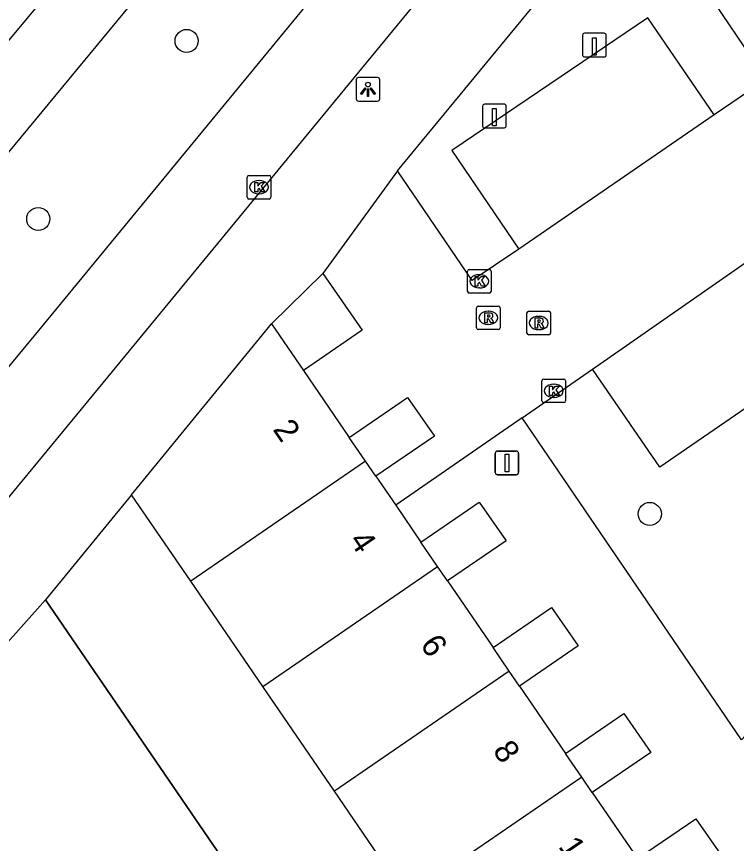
# Model space of a CAD drawing. Extents: x 155275 to 156263, y 382654 to 383635.
# Drawn here: x 155522.64 to 155553.1, y 382882.06 to 382917.07 of the extents above; entities that cross this region are included whole.
import ezdxf

# ---------------------------------------------------------------- set-up
doc = ezdxf.new("R2010")
doc.units = 0
for name, color, linetype in [('IMGEO_Afsluitpaal', 7, 'Continuous'), ('IMGEO_Boom', 7, 'Continuous'), ('IMGEO_Fietspad_gesloten', 7, 'Continuous'), ('IMGEO_Groenvoorziening', 7, 'Continuous'), ('IMGEO_Kolk', 7, 'Continuous'), ('IMGEO_Laadpaal', 7, 'Continuous'), ('IMGEO_Lichtpunt', 7, 'Continuous'), ('IMGEO_Muur', 7, 'Continuous'), ('IMGEO_Pand', 7, 'Continuous'), ('IMGEO_Pand_nummerreeks', 7, 'Continuous'), ('IMGEO_Parkeervlak_open', 7, 'Continuous'), ('IMGEO_Rijbaan_lokaal_gesloten', 7, 'Continuous'), ('IMGEO_Rijbaan_lokaal_open', 7, 'Continuous'), ('IMGEO_Rioolput', 7, 'Continuous'), ('IMGEO_Voetpad_open', 7, 'Continuous')]:
    doc.layers.add(name, color=color, linetype=linetype)

msp = doc.modelspace()

# ---------------------------------------------------------------- linework, layer by layer
at = {"layer": 'IMGEO_Afsluitpaal'}
for p, q in [((155542.897, 382897.769), (155542.897, 382898.569)), ((155542.897, 382898.569), (155542.897, 382897.769)), ((155542.997, 382898.669), (155543.787, 382898.669)), ((155543.787, 382898.669), (155542.997, 382898.669)), ((155543.887, 382898.569), (155543.887, 382897.769)), ((155543.887, 382897.769), (155543.887, 382898.569)), ((155543.787, 382897.669), (155542.997, 382897.669)), ((155542.997, 382897.669), (155543.787, 382897.669))]:
    msp.add_line(p, q, dxfattribs=at)
msp.add_lwpolyline([(155543.317, 382898.544), (155543.467, 382898.544), (155543.467, 382897.794), (155543.317, 382897.794), (155543.317, 382898.544)], dxfattribs=at)
for centre, start, end in [((155542.997, 382898.569), 90, 180), ((155542.997, 382898.569), 90, 180), ((155543.787, 382898.569), 0, 90), ((155543.787, 382898.569), 360, 90), ((155542.997, 382897.769), 180, 270), ((155542.997, 382897.769), 180, 270), ((155543.787, 382897.769), 270, 0), ((155543.787, 382897.769), 270, 0)]:
    msp.add_arc(centre, 0.1, start, end, dxfattribs=at)
at = {"layer": 'IMGEO_Boom'}
for centre in [(155529.837, 382916.032), (155523.557, 382908.496), (155549.436, 382896.009)]:
    msp.add_circle(centre, 0.489, dxfattribs=at)
at = {"layer": 'IMGEO_Fietspad_gesloten'}
for points in [[(155572.789, 382977.41), (155548.966, 382948.356), (155528.673, 382923.729), (155507.607, 382898.405), (155494.374, 382882.291)], [(155496.67, 382880.437), (155497.335, 382881.332), (155511.334, 382898.215), (155518.802, 382907.088), (155545.301, 382939.168), (155575.161, 382975.555)]]:
    msp.add_lwpolyline(points, dxfattribs=at)
at = {"layer": 'IMGEO_Groenvoorziening'}
msp.add_lwpolyline([(155552.869, 382856.181), (155549.963, 382854.195), (155523.867, 382892.372)], dxfattribs=at)
at = {"layer": 'IMGEO_Kolk'}
for p, q in [((155532.475, 382910.341), (155533.327, 382910.341)), ((155532.4, 382909.415), (155532.4, 382910.267)), ((155532.888, 382910.121), (155532.913, 382910.121)), ((155533.401, 382910.267), (155533.401, 382909.415)), ((155533.327, 382909.341), (155532.475, 382909.341)), ((155532.911, 382909.561), (155532.886, 382909.561)), ((155541.722, 382905.433), (155541.722, 382906.285)), ((155541.797, 382906.359), (155542.649, 382906.359)), ((155542.21, 382906.139), (155542.235, 382906.139)), ((155542.723, 382906.285), (155542.723, 382905.433)), ((155542.233, 382905.579), (155542.208, 382905.579)), ((155542.649, 382905.359), (155541.797, 382905.359)), ((155544.873, 382900.795), (155544.873, 382901.647)), ((155544.948, 382901.721), (155545.8, 382901.721)), ((155545.874, 382901.647), (155545.874, 382900.795)), ((155545.361, 382901.501), (155545.386, 382901.501)), ((155545.384, 382900.941), (155545.359, 382900.941)), ((155545.8, 382900.721), (155544.948, 382900.721))]:
    msp.add_line(p, q, dxfattribs=at)
for points in [[(155532.475, 382910.341), (155533.327, 382910.341)], [(155532.4, 382909.415), (155532.4, 382910.267)], [(155532.721, 382910.041), (155532.844, 382910.041), (155532.844, 382909.89), (155532.974, 382910.041), (155533.138, 382910.041), (155532.992, 382909.89), (155533.145, 382909.641), (155532.993, 382909.641), (155532.908, 382909.805), (155532.844, 382909.738), (155532.844, 382909.641), (155532.721, 382909.641), (155532.721, 382910.041)], [(155533.401, 382910.267), (155533.401, 382909.415)], [(155533.327, 382909.341), (155532.475, 382909.341)], [(155541.722, 382905.433), (155541.722, 382906.285)], [(155541.797, 382906.359), (155542.649, 382906.359)], [(155542.723, 382906.285), (155542.723, 382905.433)], [(155542.043, 382906.059), (155542.166, 382906.059), (155542.166, 382905.908), (155542.296, 382906.059), (155542.46, 382906.059), (155542.314, 382905.908), (155542.467, 382905.659), (155542.315, 382905.659), (155542.23, 382905.823), (155542.166, 382905.756), (155542.166, 382905.659), (155542.043, 382905.659), (155542.043, 382906.059)], [(155542.649, 382905.359), (155541.797, 382905.359)], [(155544.873, 382900.795), (155544.873, 382901.647)], [(155544.948, 382901.721), (155545.8, 382901.721)], [(155545.874, 382901.647), (155545.874, 382900.795)], [(155545.194, 382901.421), (155545.317, 382901.421), (155545.317, 382901.27), (155545.447, 382901.421), (155545.611, 382901.421), (155545.465, 382901.27), (155545.618, 382901.021), (155545.466, 382901.021), (155545.381, 382901.185), (155545.317, 382901.118), (155545.317, 382901.021), (155545.194, 382901.021), (155545.194, 382901.421)], [(155545.8, 382900.721), (155544.948, 382900.721)]]:
    msp.add_lwpolyline(points, dxfattribs=at)
for centre, start, end in [((155532.477, 382910.265), 91.552, 178.448), ((155532.477, 382910.265), 91.552, 178.448), ((155533.325, 382910.265), 1.552, 88.448), ((155533.325, 382910.265), 1.552, 88.448), ((155532.477, 382909.417), 181.552, 268.448), ((155532.477, 382909.417), 181.552, 268.448), ((155533.325, 382909.417), 271.552, 358.448), ((155533.325, 382909.417), 271.552, 358.448), ((155541.799, 382906.283), 91.552, 178.448), ((155541.799, 382906.283), 91.552, 178.448), ((155542.647, 382906.283), 1.552, 88.448), ((155542.647, 382906.283), 1.552, 88.448), ((155541.799, 382905.435), 181.552, 268.448), ((155541.799, 382905.435), 181.552, 268.448), ((155542.647, 382905.435), 271.552, 358.448), ((155542.647, 382905.435), 271.552, 358.448), ((155544.95, 382901.645), 91.552, 178.448), ((155544.95, 382901.645), 91.552, 178.448), ((155545.798, 382901.645), 1.552, 88.448), ((155545.798, 382901.645), 1.552, 88.448), ((155544.95, 382900.797), 181.552, 268.448), ((155544.95, 382900.797), 181.552, 268.448), ((155545.798, 382900.797), 271.552, 358.448), ((155545.798, 382900.797), 271.552, 358.448)]:
    msp.add_arc(centre, 0.0765, start, end, dxfattribs=at)
for centre, major_axis, ratio, start_param, end_param in [((155532.887, 382909.841), (-0.387, 0.002), 0.722429, 4.712389, 7.853982), ((155532.912, 382909.841), (-0.39, 0.002), 0.717154, 1.570796, 4.712389), ((155542.209, 382905.859), (-0.387, 0.002), 0.722429, 4.712389, 7.853982), ((155542.234, 382905.859), (-0.39, 0.002), 0.717154, 1.570796, 4.712389), ((155545.36, 382901.221), (-0.387, 0.002), 0.722429, 4.712389, 7.853982), ((155545.385, 382901.221), (-0.39, 0.002), 0.717154, 1.570796, 4.712389)]:
    msp.add_ellipse(centre, major_axis=major_axis, ratio=ratio, start_param=start_param, end_param=end_param, dxfattribs=at)
at = {"layer": 'IMGEO_Laadpaal'}
for p, q in [((155546.592, 382916.273), (155546.592, 382915.432)), ((155546.592, 382916.273), (155546.592, 382915.432)), ((155547.508, 382916.357), (155546.667, 382916.357)), ((155547.508, 382916.357), (155546.667, 382916.357)), ((155547.592, 382915.441), (155547.592, 382916.282)), ((155547.592, 382915.441), (155547.592, 382916.282)), ((155546.676, 382915.357), (155547.517, 382915.357)), ((155546.676, 382915.357), (155547.517, 382915.357)), ((155542.362, 382913.271), (155542.362, 382912.43)), ((155542.362, 382913.271), (155542.362, 382912.43)), ((155543.278, 382913.355), (155542.437, 382913.355)), ((155543.278, 382913.355), (155542.437, 382913.355)), ((155543.362, 382912.439), (155543.362, 382913.28)), ((155543.362, 382912.439), (155543.362, 382913.28)), ((155542.446, 382912.355), (155543.287, 382912.355)), ((155542.446, 382912.355), (155543.287, 382912.355))]:
    msp.add_line(p, q, dxfattribs=at)
for points in [[(155547.007, 382916.17), (155547.167, 382916.17), (155547.167, 382915.437), (155547.007, 382915.437), (155547.007, 382916.17)], [(155542.777, 382913.168), (155542.937, 382913.168), (155542.937, 382912.435), (155542.777, 382912.435), (155542.777, 382913.168)]]:
    msp.add_lwpolyline(points, dxfattribs=at)
for centre, start, end in [((155546.67, 382916.279), 92.4484, 184.2845), ((155546.67, 382916.279), 92.4484, 184.2845), ((155547.514, 382916.279), 2.4484, 94.2845), ((155547.514, 382916.279), 2.4484, 94.2845), ((155546.67, 382915.435), 182.4484, 274.2845), ((155546.67, 382915.435), 182.4484, 274.2845), ((155547.514, 382915.435), 272.4484, 4.2845), ((155547.514, 382915.435), 272.4484, 4.2845), ((155542.44, 382913.277), 92.4484, 184.2845), ((155542.44, 382913.277), 92.4484, 184.2845), ((155543.284, 382913.277), 2.4484, 94.2845), ((155543.284, 382913.277), 2.4484, 94.2845), ((155542.44, 382912.433), 182.4484, 274.2845), ((155542.44, 382912.433), 182.4484, 274.2845), ((155543.284, 382912.433), 272.4484, 4.2845), ((155543.284, 382912.433), 272.4484, 4.2845)]:
    msp.add_arc(centre, 0.0779, start, end, dxfattribs=at)
at = {"layer": 'IMGEO_Lichtpunt'}
for p, q in [((155537.914, 382914.482), (155537.106, 382914.482)), ((155537.914, 382914.482), (155537.106, 382914.482)), ((155537.012, 382914.387), (155537.012, 382913.58)), ((155537.012, 382914.387), (155537.012, 382913.58)), ((155538.008, 382913.58), (155538.008, 382914.387)), ((155538.008, 382913.58), (155538.008, 382914.387)), ((155537.106, 382913.486), (155537.914, 382913.486)), ((155537.106, 382913.486), (155537.914, 382913.486))]:
    msp.add_line(p, q, dxfattribs=at)
for points in [[(155537.386, 382914.051), (155537.425, 382914.023), (155537.237, 382913.761), (155537.199, 382913.788), (155537.386, 382914.051)], [(155537.488, 382914.003), (155537.535, 382914.003), (155537.535, 382913.681), (155537.488, 382913.681), (155537.488, 382914.003)], [(155537.598, 382914.023), (155537.636, 382914.05), (155537.823, 382913.788), (155537.784, 382913.76), (155537.598, 382914.023)]]:
    msp.add_lwpolyline(points, dxfattribs=at)
msp.add_circle((155537.511, 382914.185), 0.0994, dxfattribs=at)
for centre, start, end in [((155537.106, 382914.387), 90, 180), ((155537.106, 382914.387), 90, 180), ((155537.914, 382914.387), 0, 90), ((155537.914, 382914.387), 0, 90), ((155537.106, 382913.58), 180, 270), ((155537.106, 382913.58), 180, 270), ((155537.914, 382913.58), 270, 0), ((155537.914, 382913.58), 270, 360)]:
    msp.add_arc(centre, 0.0946, start, end, dxfattribs=at)
at = {"layer": 'IMGEO_Muur'}
msp.add_lwpolyline([(155527.511, 382896.822), (155523.867, 382892.372), (155549.963, 382854.195), (155552.869, 382856.181), (155554.52, 382857.31)], dxfattribs=at)
at = {"layer": 'IMGEO_Pand'}
for points in [[(155533.433, 382904.053), (155535.603, 382906.193)], [(155535.603, 382906.193), (155537.265, 382903.784), (155534.78, 382902.084)], [(155527.511, 382896.822), (155533.433, 382904.053)], [(155533.433, 382904.053), (155534.78, 382902.084)], [(155534.78, 382902.084), (155536.718, 382899.251)], [(155536.718, 382899.251), (155539.19, 382900.942), (155540.327, 382899.301), (155537.845, 382897.603)], [(155537.409, 382898.24), (155536.718, 382899.251)], [(155537.409, 382898.24), (155530.013, 382893.162)], [(155537.845, 382897.603), (155537.409, 382898.24)], [(155537.845, 382897.603), (155538.685, 382896.376)], [(155530.013, 382893.162), (155527.511, 382896.822)], [(155538.685, 382896.376), (155539.75, 382894.819)], [(155539.75, 382894.819), (155542.221, 382896.51), (155543.36, 382894.875), (155540.874, 382893.175)], [(155540.457, 382893.785), (155539.75, 382894.819)], [(155533.059, 382888.705), (155540.457, 382893.785)], [(155540.874, 382893.175), (155540.457, 382893.785)], [(155533.059, 382888.705), (155530.013, 382893.162)], [(155540.874, 382893.175), (155542.805, 382890.352)], [(155542.805, 382890.352), (155545.279, 382892.045), (155546.412, 382890.42), (155543.924, 382888.717)], [(155543.488, 382889.353), (155542.805, 382890.352)], [(155543.488, 382889.353), (155536.09, 382884.272)], [(155543.924, 382888.717), (155543.488, 382889.353)], [(155536.09, 382884.272), (155533.059, 382888.705)], [(155543.924, 382888.717), (155545.874, 382885.867)], [(155545.874, 382885.867), (155548.341, 382887.555), (155549.478, 382885.915), (155547, 382884.22)], [(155546.555, 382884.871), (155545.874, 382885.867)], [(155546.555, 382884.871), (155539.154, 382879.789)], [(155547, 382884.22), (155546.555, 382884.871)], [(155539.154, 382879.789), (155536.09, 382884.272)], [(155547, 382884.22), (155548.917, 382881.418)], [(155548.917, 382881.418), (155551.385, 382883.107), (155552.522, 382881.467), (155550.044, 382879.771)]]:
    msp.add_lwpolyline(points, dxfattribs=at)
at = {"layer": 'IMGEO_Parkeervlak_open'}
for points in [[(155564.5, 382921.36), (155561.715, 382925.5), (155551.554, 382918.563), (155554.362, 382914.404)], [(155552.163, 382912.899), (155549.358, 382917.012), (155541.06, 382911.389), (155543.897, 382907.215)], [(155557.285, 382909.289), (155560.141, 382905.057), (155549.865, 382897.984), (155547.017, 382902.134)]]:
    msp.add_lwpolyline(points, dxfattribs=at)
at = {"layer": 'IMGEO_Rijbaan_lokaal_gesloten'}
for points in [[(155500.998, 382876.481), (155523.385, 382903.532), (155571.314, 382961.825)], [(155554.945, 382936.396), (155524.977, 382899.965), (155521.205, 382895.388), (155518.222, 382891.797), (155518.138, 382891.696)]]:
    msp.add_lwpolyline(points, dxfattribs=at)
at = {"layer": 'IMGEO_Rijbaan_lokaal_open'}
for points in [[(155554.362, 382914.404), (155552.163, 382912.899)], [(155552.163, 382912.899), (155543.897, 382907.215)], [(155538.767, 382910.535), (155535.603, 382906.193)], [(155543.897, 382907.215), (155541.925, 382905.896), (155538.767, 382910.535)], [(155547.017, 382902.134), (155557.285, 382909.289)], [(155544.039, 382900.076), (155547.017, 382902.134)], [(155544.039, 382900.076), (155538.685, 382896.376)]]:
    msp.add_lwpolyline(points, dxfattribs=at)
at = {"layer": 'IMGEO_Rioolput'}
for p, q in [((155542.103, 382903.885), (155542.103, 382904.737)), ((155542.178, 382904.811), (155543.03, 382904.811)), ((155543.104, 382904.737), (155543.104, 382903.885)), ((155542.591, 382904.591), (155542.616, 382904.591)), ((155544.238, 382903.667), (155544.238, 382904.519)), ((155544.313, 382904.593), (155545.165, 382904.593)), ((155544.726, 382904.373), (155544.751, 382904.373)), ((155545.239, 382904.519), (155545.239, 382903.667)), ((155542.614, 382904.031), (155542.589, 382904.031)), ((155543.03, 382903.811), (155542.178, 382903.811)), ((155544.749, 382903.813), (155544.724, 382903.813)), ((155545.165, 382903.593), (155544.313, 382903.593))]:
    msp.add_line(p, q, dxfattribs=at)
for points in [[(155542.103, 382903.885), (155542.103, 382904.737)], [(155542.178, 382904.811), (155543.03, 382904.811)], [(155543.104, 382904.737), (155543.104, 382903.885)], [(155542.692, 382904.509), (155542.44, 382904.511), (155542.44, 382904.111)], [(155542.618, 382904.43), (155542.564, 382904.43), (155542.564, 382904.349)], [(155542.564, 382904.349), (155542.616, 382904.349)], [(155544.238, 382903.667), (155544.238, 382904.519)], [(155544.313, 382904.593), (155545.165, 382904.593)], [(155545.239, 382904.519), (155545.239, 382903.667)], [(155542.44, 382904.111), (155542.564, 382904.111), (155542.564, 382904.273), (155542.575, 382904.273)], [(155542.622, 382904.244), (155542.693, 382904.111), (155542.833, 382904.111), (155542.768, 382904.237)], [(155544.827, 382904.291), (155544.575, 382904.293), (155544.575, 382903.893)], [(155544.575, 382903.893), (155544.699, 382903.893), (155544.699, 382904.055), (155544.71, 382904.055)], [(155544.753, 382904.212), (155544.699, 382904.212), (155544.699, 382904.131)], [(155544.699, 382904.131), (155544.751, 382904.131)], [(155544.757, 382904.026), (155544.828, 382903.893), (155544.968, 382903.893), (155544.903, 382904.019)], [(155543.03, 382903.811), (155542.178, 382903.811)], [(155545.165, 382903.593), (155544.313, 382903.593)]]:
    msp.add_lwpolyline(points, dxfattribs=at)
for centre, radius, start, end in [((155542.18, 382904.735), 0.0765, 91.552, 178.448), ((155542.18, 382904.735), 0.0765, 91.552, 178.448), ((155543.028, 382904.735), 0.0765, 1.552, 88.448), ((155543.028, 382904.735), 0.0765, 1.552, 88.448), ((155542.6, 382904.538), 0.19, 274.7715, 282.9687), ((155542.624, 382904.334), 0.0964, 77.0061, 93.1865), ((155542.638, 382904.391), 0.0378, 276.6634, 79.6772), ((155542.691, 382904.399), 0.109, 350.3612, 89.416), ((155542.689, 382904.399), 0.112, 277.5842, 350.9817), ((155544.315, 382904.517), 0.0765, 91.552, 178.448), ((155544.315, 382904.517), 0.0765, 91.552, 178.448), ((155545.163, 382904.517), 0.0765, 1.552, 88.448), ((155545.163, 382904.517), 0.0765, 1.552, 88.448), ((155542.574, 382904.22), 0.0533, 26.0293, 88.6989), ((155542.673, 382904.184), 0.108, 29.5134, 73.7905), ((155544.709, 382904.002), 0.0533, 26.0293, 88.6989), ((155544.735, 382904.32), 0.19, 274.7715, 282.9687), ((155544.759, 382904.116), 0.0964, 77.0061, 93.1865), ((155544.773, 382904.173), 0.0378, 276.6634, 79.6772), ((155544.826, 382904.181), 0.109, 350.3612, 89.416), ((155544.824, 382904.181), 0.112, 277.5842, 350.9817), ((155544.808, 382903.966), 0.108, 29.5134, 73.7905), ((155542.18, 382903.887), 0.0765, 181.552, 268.448), ((155542.18, 382903.887), 0.0765, 181.552, 268.448), ((155543.028, 382903.887), 0.0765, 271.552, 358.448), ((155543.028, 382903.887), 0.0765, 271.552, 358.448), ((155544.315, 382903.669), 0.0765, 181.552, 268.448), ((155544.315, 382903.669), 0.0765, 181.552, 268.448), ((155545.163, 382903.669), 0.0765, 271.552, 358.448), ((155545.163, 382903.669), 0.0765, 271.552, 358.448)]:
    msp.add_arc(centre, radius, start, end, dxfattribs=at)
for centre, major_axis, ratio, start_param, end_param in [((155542.59, 382904.311), (-0.387, 0.002), 0.722429, 4.712389, 7.853982), ((155542.615, 382904.311), (-0.39, 0.002), 0.717154, 1.570796, 4.712389), ((155544.725, 382904.093), (-0.387, 0.002), 0.722429, 4.712389, 7.853982), ((155544.75, 382904.093), (-0.39, 0.002), 0.717154, 1.570796, 4.712389)]:
    msp.add_ellipse(centre, major_axis=major_axis, ratio=ratio, start_param=start_param, end_param=end_param, dxfattribs=at)
at = {"layer": 'IMGEO_Voetpad_open'}
for points in [[(155538.767, 382910.535), (155558.839, 382934.901)], [(155555.321, 382888.618), (155553.322, 382886.445), (155544.039, 382900.076)], [(155527.511, 382896.822), (155523.867, 382892.372)], [(155523.867, 382892.372), (155517.653, 382885.419), (155504.528, 382869.442)]]:
    msp.add_lwpolyline(points, dxfattribs=at)

# ---------------------------------------------------------------- texts
at = {"layer": 'IMGEO_Pand_nummerreeks'}
for s, rotation, p in [('2', 304.1767, (155533.459, 382899.59)), ('4', 304.1825, (155536.681, 382894.879)), ('6', 304.1767, (155539.692, 382890.477)), ('8', 304.1825, (155542.764, 382885.988)), ('10', 304.1825, (155545.54, 382881.931))]:
    msp.add_text(s, height=1, rotation=rotation, dxfattribs=at).set_placement(p)

doc.saveas('drawing.dxf')
